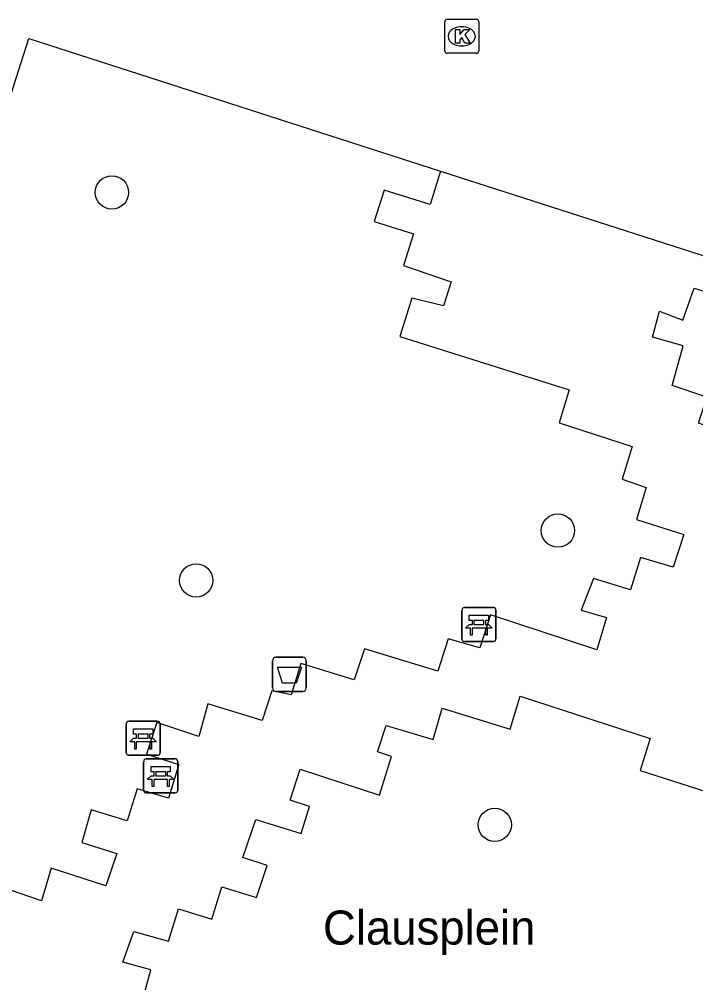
# Model space of a CAD drawing. Extents: x 160676 to 161153, y 383244 to 383713.
# Drawn here: x 161008.08 to 161027.96, y 383289.92 to 383318.23 of the extents above; entities that cross this region are included whole.
import ezdxf

# ---------------------------------------------------------------- set-up
doc = ezdxf.new("R2010")
doc.units = 0
for name, color, linetype in [('IMGEO_Afvalbak', 7, 'Continuous'), ('IMGEO_Bank', 7, 'Continuous'), ('IMGEO_Boom', 7, 'Continuous'), ('IMGEO_Kolk', 7, 'Continuous'), ('IMGEO_Openbare_ruimte_label', 7, 'Continuous'), ('IMGEO_Voetpad_open', 7, 'Continuous')]:
    doc.layers.add(name, color=color, linetype=linetype)

msp = doc.modelspace()

# ---------------------------------------------------------------- linework, layer by layer
at = {"layer": 'IMGEO_Afvalbak'}
for p, q in [((161015.521, 383298.583), (161015.521, 383299.383)), ((161015.521, 383299.383), (161015.521, 383298.583)), ((161015.621, 383299.483), (161016.411, 383299.483)), ((161016.411, 383299.483), (161015.621, 383299.483)), ((161016.511, 383299.383), (161016.511, 383298.583)), ((161016.511, 383298.583), (161016.511, 383299.383)), ((161016.411, 383298.483), (161015.621, 383298.483)), ((161015.621, 383298.483), (161016.411, 383298.483))]:
    msp.add_line(p, q, dxfattribs=at)
msp.add_lwpolyline([(161015.664, 383299.197), (161016.368, 383299.197), (161016.219, 383298.727), (161015.813, 383298.727), (161015.664, 383299.197)], dxfattribs=at)
for centre, start, end in [((161015.621, 383299.383), 90, 180), ((161015.621, 383299.383), 90, 180), ((161016.411, 383299.383), 0, 90), ((161016.411, 383299.383), 360, 90), ((161015.621, 383298.583), 180, 270), ((161015.621, 383298.583), 180, 270), ((161016.411, 383298.583), 270, 0), ((161016.411, 383298.583), 270, 0)]:
    msp.add_arc(centre, 0.1, start, end, dxfattribs=at)
at = {"layer": 'IMGEO_Bank'}
for p, q in [((161021.161, 383300.946), (161022.002, 383300.946)), ((161022.002, 383300.946), (161021.161, 383300.946)), ((161021.086, 383300.021), (161021.086, 383300.862)), ((161021.086, 383300.862), (161021.086, 383300.021)), ((161022.086, 383300.871), (161022.086, 383300.03)), ((161022.086, 383300.03), (161022.086, 383300.871)), ((161021.783, 383300.344), (161021.39, 383300.344)), ((161021.395, 383300.452), (161021.395, 383300.558)), ((161021.439, 383300.558), (161021.439, 383300.452)), ((161021.727, 383300.564), (161021.445, 383300.564)), ((161021.445, 383300.446), (161021.727, 383300.446)), ((161021.733, 383300.452), (161021.733, 383300.558)), ((161021.777, 383300.558), (161021.777, 383300.452)), ((161022.011, 383299.946), (161021.17, 383299.946)), ((161021.17, 383299.946), (161022.011, 383299.946)), ((161011.218, 383296.681), (161011.218, 383297.522)), ((161011.218, 383297.522), (161011.218, 383296.681)), ((161011.293, 383297.606), (161012.134, 383297.606)), ((161012.134, 383297.606), (161011.293, 383297.606)), ((161012.218, 383297.531), (161012.218, 383296.69)), ((161012.218, 383296.69), (161012.218, 383297.531)), ((161011.915, 383297.004), (161011.522, 383297.004)), ((161011.527, 383297.112), (161011.527, 383297.218)), ((161011.571, 383297.218), (161011.571, 383297.112)), ((161011.859, 383297.224), (161011.577, 383297.224)), ((161011.577, 383297.106), (161011.859, 383297.106)), ((161011.865, 383297.112), (161011.865, 383297.218)), ((161011.909, 383297.218), (161011.909, 383297.112)), ((161012.143, 383296.606), (161011.302, 383296.606)), ((161011.302, 383296.606), (161012.143, 383296.606)), ((161011.733, 383295.576), (161011.733, 383296.417)), ((161011.733, 383296.417), (161011.733, 383295.576)), ((161011.808, 383296.501), (161012.649, 383296.501)), ((161012.649, 383296.501), (161011.808, 383296.501)), ((161012.733, 383296.426), (161012.733, 383295.585)), ((161012.733, 383295.585), (161012.733, 383296.426)), ((161012.042, 383296.007), (161012.042, 383296.113)), ((161012.086, 383296.113), (161012.086, 383296.007)), ((161012.374, 383296.119), (161012.092, 383296.119)), ((161012.38, 383296.007), (161012.38, 383296.113)), ((161012.424, 383296.113), (161012.424, 383296.007)), ((161012.43, 383295.899), (161012.037, 383295.899)), ((161012.092, 383296.001), (161012.374, 383296.001)), ((161012.658, 383295.501), (161011.817, 383295.501)), ((161011.817, 383295.501), (161012.658, 383295.501))]:
    msp.add_line(p, q, dxfattribs=at)
for points in [[(161021.389, 383300.564), (161021.303, 383300.564), (161021.303, 383300.725), (161021.866, 383300.725), (161021.866, 383300.564), (161021.783, 383300.564)], [(161021.333, 383300.344), (161021.191, 383300.344), (161021.303, 383300.446), (161021.389, 383300.446)], [(161021.783, 383300.446), (161021.866, 383300.446), (161021.978, 383300.344), (161021.839, 383300.344)], [(161021.383, 383300.337), (161021.383, 383300.13), (161021.34, 383300.13), (161021.34, 383300.337)], [(161021.833, 383300.337), (161021.833, 383300.13), (161021.789, 383300.13), (161021.789, 383300.337)], [(161011.521, 383297.224), (161011.435, 383297.224), (161011.435, 383297.385), (161011.998, 383297.385), (161011.998, 383297.224), (161011.915, 383297.224)], [(161011.465, 383297.004), (161011.323, 383297.004), (161011.435, 383297.106), (161011.521, 383297.106)], [(161011.515, 383296.997), (161011.515, 383296.79), (161011.472, 383296.79), (161011.472, 383296.997)], [(161011.915, 383297.106), (161011.998, 383297.106), (161012.11, 383297.004), (161011.971, 383297.004)], [(161011.965, 383296.997), (161011.965, 383296.79), (161011.921, 383296.79), (161011.921, 383296.997)], [(161012.036, 383296.119), (161011.95, 383296.119), (161011.95, 383296.28), (161012.513, 383296.28), (161012.513, 383296.119), (161012.43, 383296.119)], [(161011.98, 383295.899), (161011.838, 383295.899), (161011.95, 383296.001), (161012.036, 383296.001)], [(161012.03, 383295.892), (161012.03, 383295.685), (161011.987, 383295.685), (161011.987, 383295.892)], [(161012.43, 383296.001), (161012.513, 383296.001), (161012.625, 383295.899), (161012.486, 383295.899)], [(161012.48, 383295.892), (161012.48, 383295.685), (161012.436, 383295.685), (161012.436, 383295.892)]]:
    msp.add_lwpolyline(points, dxfattribs=at)
for centre, radius, start, end in [((161021.164, 383300.868), 0.0779, 92.4484, 184.2845), ((161021.164, 383300.868), 0.0779, 92.4484, 184.2845), ((161022.008, 383300.868), 0.0779, 2.4484, 94.2845), ((161022.008, 383300.868), 0.0779, 2.4484, 94.2845), ((161021.333, 383300.337), 0.00671, 2.8957, 87.1043), ((161021.39, 383300.337), 0.00671, 92.8957, 177.1043), ((161021.388, 383300.557), 0.00671, 2.8957, 87.1043), ((161021.388, 383300.453), 0.00671, 272.8957, 357.1043), ((161021.445, 383300.557), 0.00671, 92.8957, 177.1043), ((161021.445, 383300.453), 0.00671, 182.8957, 267.1043), ((161021.727, 383300.557), 0.00671, 2.8957, 87.1043), ((161021.727, 383300.453), 0.00671, 272.8957, 357.1043), ((161021.784, 383300.557), 0.00671, 92.8957, 177.1043), ((161021.784, 383300.453), 0.00671, 182.8957, 267.1043), ((161021.782, 383300.337), 0.00671, 2.8957, 87.1043), ((161021.839, 383300.337), 0.00671, 92.8957, 177.1043), ((161021.164, 383300.024), 0.0779, 182.4484, 274.2845), ((161021.164, 383300.024), 0.0779, 182.4484, 274.2845), ((161022.008, 383300.024), 0.0779, 272.4484, 4.2845), ((161022.008, 383300.024), 0.0779, 272.4484, 4.2845), ((161011.296, 383297.528), 0.0779, 92.4484, 184.2845), ((161011.296, 383297.528), 0.0779, 92.4484, 184.2845), ((161012.14, 383297.528), 0.0779, 2.4484, 94.2845), ((161012.14, 383297.528), 0.0779, 2.4484, 94.2845), ((161011.465, 383296.997), 0.00671, 2.8957, 87.1043), ((161011.522, 383296.997), 0.00671, 92.8957, 177.1043), ((161011.52, 383297.217), 0.00671, 2.8957, 87.1043), ((161011.52, 383297.113), 0.00671, 272.8957, 357.1043), ((161011.577, 383297.217), 0.00671, 92.8957, 177.1043), ((161011.577, 383297.113), 0.00671, 182.8957, 267.1043), ((161011.859, 383297.217), 0.00671, 2.8957, 87.1043), ((161011.859, 383297.113), 0.00671, 272.8957, 357.1043), ((161011.916, 383297.217), 0.00671, 92.8957, 177.1043), ((161011.916, 383297.113), 0.00671, 182.8957, 267.1043), ((161011.914, 383296.997), 0.00671, 2.8957, 87.1043), ((161011.971, 383296.997), 0.00671, 92.8957, 177.1043), ((161011.296, 383296.684), 0.0779, 182.4484, 274.2845), ((161011.296, 383296.684), 0.0779, 182.4484, 274.2845), ((161012.14, 383296.684), 0.0779, 272.4484, 4.2845), ((161012.14, 383296.684), 0.0779, 272.4484, 4.2845), ((161011.811, 383296.423), 0.0779, 92.4484, 184.2845), ((161011.811, 383296.423), 0.0779, 92.4484, 184.2845), ((161012.655, 383296.423), 0.0779, 2.4484, 94.2845), ((161012.655, 383296.423), 0.0779, 2.4484, 94.2845), ((161012.035, 383296.112), 0.00671, 2.8957, 87.1043), ((161012.092, 383296.112), 0.00671, 92.8957, 177.1043), ((161012.374, 383296.112), 0.00671, 2.8957, 87.1043), ((161012.431, 383296.112), 0.00671, 92.8957, 177.1043), ((161011.98, 383295.892), 0.00671, 2.8957, 87.1043), ((161012.037, 383295.892), 0.00671, 92.8957, 177.1043), ((161012.035, 383296.008), 0.00671, 272.8957, 357.1043), ((161012.092, 383296.008), 0.00671, 182.8957, 267.1043), ((161012.374, 383296.008), 0.00671, 272.8957, 357.1043), ((161012.431, 383296.008), 0.00671, 182.8957, 267.1043), ((161012.429, 383295.892), 0.00671, 2.8957, 87.1043), ((161012.486, 383295.892), 0.00671, 92.8957, 177.1043), ((161011.811, 383295.579), 0.0779, 182.4484, 274.2845), ((161011.811, 383295.579), 0.0779, 182.4484, 274.2845), ((161012.655, 383295.579), 0.0779, 272.4484, 4.2845), ((161012.655, 383295.579), 0.0779, 272.4484, 4.2845)]:
    msp.add_arc(centre, radius, start, end, dxfattribs=at)
at = {"layer": 'IMGEO_Boom'}
for centre in [(161010.8, 383313.141), (161023.908, 383303.206), (161013.277, 383301.742), (161022.051, 383294.563)]:
    msp.add_circle(centre, 0.489, dxfattribs=at)
at = {"layer": 'IMGEO_Kolk'}
for p, q in [((161020.655, 383318.225), (161021.507, 383318.225)), ((161020.58, 383317.299), (161020.58, 383318.151)), ((161021.068, 383318.005), (161021.093, 383318.005)), ((161021.581, 383318.151), (161021.581, 383317.299)), ((161021.091, 383317.445), (161021.066, 383317.445)), ((161021.507, 383317.225), (161020.655, 383317.225))]:
    msp.add_line(p, q, dxfattribs=at)
for points in [[(161020.655, 383318.225), (161021.507, 383318.225)], [(161020.58, 383317.299), (161020.58, 383318.151)], [(161020.901, 383317.925), (161021.024, 383317.925), (161021.024, 383317.774), (161021.154, 383317.925), (161021.318, 383317.925), (161021.172, 383317.774), (161021.325, 383317.525), (161021.173, 383317.525), (161021.088, 383317.689), (161021.024, 383317.622), (161021.024, 383317.525), (161020.901, 383317.525), (161020.901, 383317.925)], [(161021.581, 383318.151), (161021.581, 383317.299)], [(161021.507, 383317.225), (161020.655, 383317.225)]]:
    msp.add_lwpolyline(points, dxfattribs=at)
for centre, start, end in [((161020.657, 383318.149), 91.552, 178.448), ((161020.657, 383318.149), 91.552, 178.448), ((161021.505, 383318.149), 1.552, 88.448), ((161021.505, 383318.149), 1.552, 88.448), ((161020.657, 383317.301), 181.552, 268.448), ((161020.657, 383317.301), 181.552, 268.448), ((161021.505, 383317.301), 271.552, 358.448), ((161021.505, 383317.301), 271.552, 358.448)]:
    msp.add_arc(centre, 0.0765, start, end, dxfattribs=at)
for centre, major_axis, ratio, start_param, end_param in [((161021.067, 383317.725), (-0.387, 0.002), 0.722429, 4.712389, 7.853982), ((161021.092, 383317.725), (-0.39, 0.002), 0.717154, 1.570796, 4.712389)]:
    msp.add_ellipse(centre, major_axis=major_axis, ratio=ratio, start_param=start_param, end_param=end_param, dxfattribs=at)
at = {"layer": 'IMGEO_Voetpad_open'}
for points in [[(160999.79, 383290.864), (161008.359, 383317.657), (161020.455, 383313.768)], [(161020.455, 383313.768), (161020.156, 383312.782), (161018.799, 383313.201), (161018.509, 383312.286), (161019.661, 383311.926), (161019.372, 383310.996), (161020.767, 383310.514), (161020.541, 383309.81), (161019.617, 383310.033), (161019.264, 383308.904), (161024.235, 383307.338), (161023.947, 383306.371), (161026.093, 383305.675), (161025.799, 383304.712), (161026.497, 383304.473), (161026.22, 383303.531), (161027.604, 383303.092), (161027.295, 383302.135), (161026.334, 383302.411), (161026.042, 383301.469), (161024.952, 383301.796), (161024.593, 383300.873), (161025.332, 383300.651), (161025.049, 383299.699), (161021.922, 383300.729), (161021.609, 383299.757), (161020.678, 383300.024), (161020.382, 383299.08), (161018.223, 383299.729), (161017.924, 383298.818), (161016.356, 383299.303), (161016.068, 383298.385), (161015.503, 383298.5), (161015.219, 383297.625), (161013.615, 383298.116), (161013.352, 383297.155), (161012.125, 383297.572), (161011.812, 383296.634), (161012.766, 383296.339), (161012.464, 383295.342), (161011.539, 383295.619), (161011.252, 383294.683), (161010.191, 383295.008), (161009.912, 383294.046), (161010.949, 383293.72), (161010.622, 383292.773), (161009.01, 383293.288), (161008.728, 383292.331), (161007.494, 383292.749)], [(161020.455, 383313.768), (161029.994, 383310.701)], [(161033.388, 383309.609), (161033.111, 383308.651), (161033.666, 383308.484), (161033.431, 383307.723), (161032.471, 383308.012), (161032.129, 383306.903), (161033.061, 383306.57), (161032.831, 383305.832), (161032.024, 383306.08), (161031.735, 383305.158), (161030.992, 383305.374), (161030.672, 383304.434), (161028.611, 383305.098), (161028.907, 383306.061), (161028.038, 383306.357), (161028.281, 383307.126), (161027.262, 383307.47), (161027.588, 383308.632), (161026.684, 383308.883), (161026.889, 383309.648), (161027.583, 383309.39), (161027.916, 383310.325), (161029.691, 383309.783), (161029.994, 383310.701)], [(161011.665, 383289.292), (161011.947, 383290.301), (161011.122, 383290.524), (161011.441, 383291.426), (161012.468, 383291.146), (161012.759, 383292.094), (161013.737, 383291.787), (161014.027, 383292.746), (161015.05, 383292.427), (161015.363, 383293.37), (161014.652, 383293.604), (161015.033, 383294.716), (161016.358, 383294.311), (161016.607, 383295.097), (161016.036, 383295.283), (161016.335, 383296.195), (161018.662, 383295.437), (161019.015, 383296.571), (161018.601, 383296.703), (161018.861, 383297.48), (161020.24, 383297.073), (161020.505, 383297.985), (161022.507, 383297.376), (161022.794, 383298.344), (161026.615, 383297.097), (161026.327, 383296.159), (161029.478, 383295.151)]]:
    msp.add_lwpolyline(points, dxfattribs=at)

# ---------------------------------------------------------------- texts
at = {"layer": 'IMGEO_Openbare_ruimte_label'}
msp.add_text('Clausplein', height=1, dxfattribs=at).set_placement((161017.003, 383291.045))

doc.saveas('drawing.dxf')
